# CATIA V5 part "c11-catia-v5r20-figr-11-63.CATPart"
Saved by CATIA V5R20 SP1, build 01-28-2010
Part number: Part2
Bounding box of the stored display mesh (mm): x -69 to 69, y -70.588 to 84.546, z -60.219 to 83.037
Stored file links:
  D:\v5_r20\psrt_files_downloaded\c11\c11-catia-v5r20-figr-11-63.CATPart
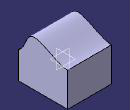
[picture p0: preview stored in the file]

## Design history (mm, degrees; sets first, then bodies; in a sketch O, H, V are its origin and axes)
Set1
  Extrude1: Element1 Sketch2, Lim1 134, Lim2 101, Direction yz-plane
Body1 (main body)
  Sketch1 on yz-plane, origin (0, 0, 0), H (0, 1, 0), V (0, 0, 1)
    line L1 (-70.5879, 56.2311) -> (84.546, 56.2311)
    line L2 (84.546, 56.2311) -> (84.546, -60.2191)
    line L3 (84.546, -60.2191) -> (-70.5879, -60.2191)
    line L4 (-70.5879, -60.2191) -> (-70.5879, 56.2311)
    horizontal: L1 H, L3 H
    vertical: L2 V, L4 V
  Pad1: profile Sketch1, direction (1, 0, 0), length 69, mirrored extent
  SewSurface1: SplitPlane Extrude1, SewingRemoveFace face of Pad1
  Sketch2 on yz-plane, origin (0, 0, 0), H (0, 1, 0), V (0, 0, 1)
    spline S1 through (-101.2957, 16.3509) (-51.8443, 49.0526) (-38.418, 74.5863) (34.1283, 62.9515) (100.0993, 49.0526)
